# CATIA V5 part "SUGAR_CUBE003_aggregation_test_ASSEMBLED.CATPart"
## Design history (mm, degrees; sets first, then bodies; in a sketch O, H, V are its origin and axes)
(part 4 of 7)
Body30 "sugar_cube003_Bd002"
  Line194: type PtDir, RefPoint Point22, Direction edge [XY plane of AxisSystem1 | ZX plane of AxisSystem1], Start 0, End 5181.6 {= Body30.X1}
  Line195: type PtDir, RefPoint Point22, Direction edge [XY plane of AxisSystem1 | ZX plane of AxisSystem1], Start 0, End 5791.2 {= Body30.X2}
  Line196: type PtDir, RefPoint Point22, Direction edge [YZ plane of AxisSystem1 | XY plane of AxisSystem1], Start 0, End 5791.2 {= Body30.Y1}
  Line197: type PtDir, RefPoint Point22, Direction edge [YZ plane of AxisSystem1 | XY plane of AxisSystem1], Start 0, End 5486.4 {= Body30.Y2}
  Line198: type PtDir, RefPoint Point22, Direction edge [ZX plane of AxisSystem1 | YZ plane of AxisSystem1], Start 0, End 3962.4 {= Body30.Z1}
  Line199: type PtDir, RefPoint Point22, Direction edge [ZX plane of AxisSystem1 | YZ plane of AxisSystem1], Start 0, End 6096 {= Body30.Z2}
  Plane375: type Normal, Curve Line194, RefPoint vertex of Line194
  Plane376: type Normal, Curve Line195, RefPoint vertex of Line195
  Plane377: type Normal, Curve Line196, RefPoint vertex of Line196
  Plane378: type Normal, Curve Line197, RefPoint vertex of Line197
  Plane379: type Normal, Curve Line198, RefPoint vertex of Line198
  Plane380: type Normal, Curve Line199, RefPoint vertex of Line199
  Plane381: type 3Points, Element1 Point22, Element2 vertex of Line196, Element3 vertex of Line194
  Intersect561: ToIntersect1 Plane377, ToIntersect2 Plane376
  Intersect562: ToIntersect1 Plane375, ToIntersect2 Plane377
  Intersect563: ToIntersect1 Plane375, ToIntersect2 Plane378
  Intersect564: ToIntersect1 Plane378, ToIntersect2 Plane376
  MultiSel29
  LineCorner29: Elements ({intersect ToIntersect1 Plane381, ToIntersect2 Intersect563}; {intersect ToIntersect1 Plane381, ToIntersect2 Intersect564}; {intersect ToIntersect1 Plane381, ToIntersect2 Intersect561}; {intersect ToIntersect1 Plane381, ToIntersect2 Intersect562})
  Pad114: profile LineCorner29, up to Plane379, opposite side up to Plane380, deactivated
  Plane382: type Offset, RefPlane Plane378, Offset 609.6 {= thickness}
  Plane383: type Offset, RefPlane Plane377, Offset 609.6 {= thickness}, reversed
  Plane384: type Offset, RefPlane Plane375, Offset 609.6 {= thickness}, reversed
  Plane385: type Offset, RefPlane Plane376, Offset 609.6 {= thickness}
  Plane386: type Offset, RefPlane Plane380, Offset 609.6 {= thickness}
  Plane387: type Offset, RefPlane Plane379, Offset 609.6 {= thickness}, reversed
  Intersect565: ToIntersect1 Plane382, ToIntersect2 Plane375
  Intersect566: ToIntersect1 Plane383, ToIntersect2 Plane375
  Intersect567: ToIntersect1 Plane386, ToIntersect2 Plane375
  Intersect568: ToIntersect1 Plane387, ToIntersect2 Plane375
  Trim337: Trimmed (Intersect565; Intersect568)
  Trim338: Trimmed (Trim337; Intersect566)
  Trim339: Trimmed (Trim338; Intersect567)
  Pocket118: profile Trim339, up to Plane385, deactivated
  Pad115: profile LineCorner29, up to Plane379, opposite side up to Plane380, deactivated
  Intersect569: ToIntersect1 Plane383, ToIntersect2 Plane376
  Intersect570: ToIntersect1 Plane376, ToIntersect2 Plane382
  Intersect571: ToIntersect1 Plane386, ToIntersect2 Plane376
  Intersect572: ToIntersect1 Plane387, ToIntersect2 Plane376
  Trim340: Trimmed (Intersect572; Intersect569)
  Trim341: Trimmed (Trim340; Intersect571)
  Trim342: Trimmed (Trim341; Intersect570)
  Pocket119: profile Trim342, up to Plane384, deactivated
  Intersect573: ToIntersect1 Plane385, ToIntersect2 Plane378
  Intersect574: ToIntersect1 Plane386, ToIntersect2 Plane378
  Intersect575: ToIntersect1 Plane378, ToIntersect2 Plane384
  Intersect576: ToIntersect1 Plane387, ToIntersect2 Plane378
  Trim343: Trimmed (Intersect573; Intersect576)
  Trim344: Trimmed (Trim343; Intersect575)
  Trim345: Trimmed (Trim344; Intersect574)
  Pad116: profile LineCorner29, up to Plane379, opposite side up to Plane380, deactivated
  Pocket120: profile Trim345, up to Plane383, deactivated
  Intersect577: ToIntersect1 Plane384, ToIntersect2 Plane377
  Intersect578: ToIntersect1 Plane386, ToIntersect2 Plane377
  Intersect579: ToIntersect1 Plane385, ToIntersect2 Plane377
  Intersect580: ToIntersect1 Plane387, ToIntersect2 Plane377
  Trim346: Trimmed (Intersect577; Intersect580)
  Trim347: Trimmed (Trim346; Intersect579)
  Trim348: Trimmed (Trim347; Intersect578)
  Pad117: profile LineCorner29, up to Plane379, opposite side up to Plane380, deactivated
  Pocket121: profile Trim348, up to Plane382, deactivated
Body31 "sugar_cube003_Be002"
  Line200: type PtDir, RefPoint Point18, Direction edge [XY plane of AxisSystem1 | ZX plane of AxisSystem1], Start 0, End 4267.2 {= Body31.X1}
  Line201: type PtDir, RefPoint Point18, Direction edge [XY plane of AxisSystem1 | ZX plane of AxisSystem1], Start 0, End 3962.4 {= Body31.X2}
  Line202: type PtDir, RefPoint Point18, Direction edge [YZ plane of AxisSystem1 | XY plane of AxisSystem1], Start 0, End 5486.4 {= Body31.Y1}
  Line203: type PtDir, RefPoint Point18, Direction edge [YZ plane of AxisSystem1 | XY plane of AxisSystem1], Start 0, End 4876.8 {= Body31.Y2}
  Line204: type PtDir, RefPoint Point18, Direction edge [ZX plane of AxisSystem1 | YZ plane of AxisSystem1], Start 0, End 4876.8 {= Body31.Z1}
  Line205: type PtDir, RefPoint Point18, Direction edge [ZX plane of AxisSystem1 | YZ plane of AxisSystem1], Start 0, End 4572 {= Body31.Z2}
  Plane388: type Normal, Curve Line200, RefPoint vertex of Line200
  Plane389: type Normal, Curve Line201, RefPoint vertex of Line201
  Plane390: type Normal, Curve Line202, RefPoint vertex of Line202
  Plane391: type Normal, Curve Line203, RefPoint vertex of Line203
  Plane392: type Normal, Curve Line204, RefPoint vertex of Line204
  Plane393: type Normal, Curve Line205, RefPoint vertex of Line205
  Plane394: type 3Points, Element1 Point18, Element2 vertex of Line202, Element3 vertex of Line200
  Intersect581: ToIntersect1 Plane390, ToIntersect2 Plane389
  Intersect582: ToIntersect1 Plane388, ToIntersect2 Plane390
  Intersect583: ToIntersect1 Plane388, ToIntersect2 Plane391
  Intersect584: ToIntersect1 Plane391, ToIntersect2 Plane389
  MultiSel30
  LineCorner30: Elements ({intersect ToIntersect1 Plane394, ToIntersect2 Intersect583}; {intersect ToIntersect1 Plane394, ToIntersect2 Intersect584}; {intersect ToIntersect1 Plane394, ToIntersect2 Intersect581}; {intersect ToIntersect1 Plane394, ToIntersect2 Intersect582})
  Pad118: profile LineCorner30, up to Plane392, opposite side up to Plane393
  Plane395: type Offset, RefPlane Plane391, Offset 609.6 {= thickness}
  Plane396: type Offset, RefPlane Plane390, Offset 609.6 {= thickness}, reversed
  Plane397: type Offset, RefPlane Plane388, Offset 609.6 {= thickness}, reversed
  Plane398: type Offset, RefPlane Plane389, Offset 609.6 {= thickness}
  Plane399: type Offset, RefPlane Plane393, Offset 609.6 {= thickness}
  Plane400: type Offset, RefPlane Plane392, Offset 609.6 {= thickness}, reversed
  Intersect585: ToIntersect1 Plane395, ToIntersect2 Plane388
  Intersect586: ToIntersect1 Plane396, ToIntersect2 Plane388
  Intersect587: ToIntersect1 Plane399, ToIntersect2 Plane388
  Intersect588: ToIntersect1 Plane400, ToIntersect2 Plane388
  Trim349: Trimmed (Intersect585; Intersect588)
  Trim350: Trimmed (Trim349; Intersect586)
  Trim351: Trimmed (Trim350; Intersect587)
  Pocket122: profile Trim351, up to Plane398, deactivated
  Pad119: profile LineCorner30, up to Plane392, opposite side up to Plane393, deactivated
  Intersect589: ToIntersect1 Plane396, ToIntersect2 Plane389
  Intersect590: ToIntersect1 Plane389, ToIntersect2 Plane395
  Intersect591: ToIntersect1 Plane399, ToIntersect2 Plane389
  Intersect592: ToIntersect1 Plane400, ToIntersect2 Plane389
  Trim352: Trimmed (Intersect592; Intersect589)
  Trim353: Trimmed (Trim352; Intersect591)
  Trim354: Trimmed (Trim353; Intersect590)
  Pocket123: profile Trim354, up to Plane397, deactivated
  Intersect593: ToIntersect1 Plane398, ToIntersect2 Plane391
  Intersect594: ToIntersect1 Plane399, ToIntersect2 Plane391
  Intersect595: ToIntersect1 Plane391, ToIntersect2 Plane397
  Intersect596: ToIntersect1 Plane400, ToIntersect2 Plane391
  Trim355: Trimmed (Intersect593; Intersect596)
  Trim356: Trimmed (Trim355; Intersect595)
  Trim357: Trimmed (Trim356; Intersect594)
  Pad120: profile LineCorner30, up to Plane392, opposite side up to Plane393, deactivated
  Pocket124: profile Trim357, up to Plane396, deactivated
  Intersect597: ToIntersect1 Plane397, ToIntersect2 Plane390
  Intersect598: ToIntersect1 Plane399, ToIntersect2 Plane390
  Intersect599: ToIntersect1 Plane398, ToIntersect2 Plane390
  Intersect600: ToIntersect1 Plane400, ToIntersect2 Plane390
  Trim358: Trimmed (Intersect597; Intersect600)
  Trim359: Trimmed (Trim358; Intersect599)
  Trim360: Trimmed (Trim359; Intersect598)
  Pad121: profile LineCorner30, up to Plane392, opposite side up to Plane393, deactivated
  Pocket125: profile Trim360, up to Plane395, deactivated
Body32 "sugar_cube003_Ba003"
  Line206: type PtDir, RefPoint Point35, Direction edge [XY plane of AxisSystem1 | ZX plane of AxisSystem1], Start 0, End 3048 {= Body32.X1}
  Line207: type PtDir, RefPoint Point35, Direction edge [XY plane of AxisSystem1 | ZX plane of AxisSystem1], Start 0, End 3962.4 {= Body32.X2}
  Line208: type PtDir, RefPoint Point35, Direction edge [YZ plane of AxisSystem1 | XY plane of AxisSystem1], Start 0, End 5791.2 {= Body32.Y1}
  Line209: type PtDir, RefPoint Point35, Direction edge [YZ plane of AxisSystem1 | XY plane of AxisSystem1], Start 0, End 3048 {= Body32.Y2}
  Line210: type PtDir, RefPoint Point35, Direction edge [ZX plane of AxisSystem1 | YZ plane of AxisSystem1], Start 0, End 5181.6 {= Body32.Z1}
  Line211: type PtDir, RefPoint Point35, Direction edge [ZX plane of AxisSystem1 | YZ plane of AxisSystem1], Start 0, End 4572 {= Body32.Z2}
  Plane401: type Normal, Curve Line206, RefPoint vertex of Line206
  Plane402: type Normal, Curve Line207, RefPoint vertex of Line207
  Plane403: type Normal, Curve Line208, RefPoint vertex of Line208
  Plane404: type Normal, Curve Line209, RefPoint vertex of Line209
  Plane405: type Normal, Curve Line210, RefPoint vertex of Line210
  Plane406: type Normal, Curve Line211, RefPoint vertex of Line211
  Plane407: type 3Points, Element1 Point35, Element2 vertex of Line208, Element3 vertex of Line206
  Intersect601: ToIntersect1 Plane403, ToIntersect2 Plane402
  Intersect602: ToIntersect1 Plane401, ToIntersect2 Plane403
  Intersect603: ToIntersect1 Plane401, ToIntersect2 Plane404
  Intersect604: ToIntersect1 Plane404, ToIntersect2 Plane402
  MultiSel31
  LineCorner31: Elements ({intersect ToIntersect1 Plane407, ToIntersect2 Intersect603}; {intersect ToIntersect1 Plane407, ToIntersect2 Intersect604}; {intersect ToIntersect1 Plane407, ToIntersect2 Intersect601}; {intersect ToIntersect1 Plane407, ToIntersect2 Intersect602})
  Pad122: profile LineCorner31, up to Plane405, opposite side up to Plane406, deactivated
  Plane408: type Offset, RefPlane Plane404, Offset 609.6 {= thickness}
  Plane409: type Offset, RefPlane Plane403, Offset 609.6 {= thickness}, reversed
  Plane410: type Offset, RefPlane Plane401, Offset 609.6 {= thickness}, reversed
  Plane411: type Offset, RefPlane Plane402, Offset 609.6 {= thickness}
  Plane412: type Offset, RefPlane Plane406, Offset 609.6 {= thickness}
  Plane413: type Offset, RefPlane Plane405, Offset 609.6 {= thickness}, reversed
  Intersect605: ToIntersect1 Plane408, ToIntersect2 Plane401
  Intersect606: ToIntersect1 Plane409, ToIntersect2 Plane401
  Intersect607: ToIntersect1 Plane412, ToIntersect2 Plane401
  Intersect608: ToIntersect1 Plane413, ToIntersect2 Plane401
  Trim361: Trimmed (Intersect605; Intersect608)
  Trim362: Trimmed (Trim361; Intersect606)
  Trim363: Trimmed (Trim362; Intersect607)
  Pocket126: profile Trim363, up to Plane411, deactivated
  Pad123: profile LineCorner31, up to Plane405, opposite side up to Plane406, deactivated
  Intersect609: ToIntersect1 Plane409, ToIntersect2 Plane402
  Intersect610: ToIntersect1 Plane402, ToIntersect2 Plane408
  Intersect611: ToIntersect1 Plane412, ToIntersect2 Plane402
  Intersect612: ToIntersect1 Plane413, ToIntersect2 Plane402
  Trim364: Trimmed (Intersect612; Intersect609)
  Trim365: Trimmed (Trim364; Intersect611)
  Trim366: Trimmed (Trim365; Intersect610)
  Pocket127: profile Trim366, up to Plane410, deactivated
  Intersect613: ToIntersect1 Plane411, ToIntersect2 Plane404
  Intersect614: ToIntersect1 Plane412, ToIntersect2 Plane404
  Intersect615: ToIntersect1 Plane404, ToIntersect2 Plane410
  Intersect616: ToIntersect1 Plane413, ToIntersect2 Plane404
  Trim367: Trimmed (Intersect613; Intersect616)
  Trim368: Trimmed (Trim367; Intersect615)
  Trim369: Trimmed (Trim368; Intersect614)
  Pad124: profile LineCorner31, up to Plane405, opposite side up to Plane406, deactivated
  Pocket128: profile Trim369, up to Plane409, deactivated
  Intersect617: ToIntersect1 Plane410, ToIntersect2 Plane403
  Intersect618: ToIntersect1 Plane412, ToIntersect2 Plane403
  Intersect619: ToIntersect1 Plane411, ToIntersect2 Plane403
  Intersect620: ToIntersect1 Plane413, ToIntersect2 Plane403
  Trim370: Trimmed (Intersect617; Intersect620)
  Trim371: Trimmed (Trim370; Intersect619)
  Trim372: Trimmed (Trim371; Intersect618)
  Pad125: profile LineCorner31, up to Plane405, opposite side up to Plane406, deactivated
  Pocket129: profile Trim372, up to Plane408, deactivated
Body33 "sugar_cube003Bb003"
  Line212: type PtDir, RefPoint Point31, Direction edge [XY plane of AxisSystem1 | ZX plane of AxisSystem1], Start 0, End 5791.2 {= Body33.X1}
  Line213: type PtDir, RefPoint Point31, Direction edge [XY plane of AxisSystem1 | ZX plane of AxisSystem1], Start 0, End 4267.2 {= Body33.X2}
  Line214: type PtDir, RefPoint Point31, Direction edge [YZ plane of AxisSystem1 | XY plane of AxisSystem1], Start 0, End 5486.4 {= Body33.Y1}
  Line215: type PtDir, RefPoint Point31, Direction edge [YZ plane of AxisSystem1 | XY plane of AxisSystem1], Start 0, End 6096 {= Body33.Y2}
  Line216: type PtDir, RefPoint Point31, Direction edge [ZX plane of AxisSystem1 | YZ plane of AxisSystem1], Start 0, End 4267.2 {= Body33.Z1}
  Line217: type PtDir, RefPoint Point31, Direction edge [ZX plane of AxisSystem1 | YZ plane of AxisSystem1], Start 0, End 5486.4 {= Body33.Z2}
  Plane414: type Normal, Curve Line212, RefPoint vertex of Line212
  Plane415: type Normal, Curve Line213, RefPoint vertex of Line213
  Plane416: type Normal, Curve Line214, RefPoint vertex of Line214
  Plane417: type Normal, Curve Line215, RefPoint vertex of Line215
  Plane418: type Normal, Curve Line216, RefPoint vertex of Line216
  Plane419: type Normal, Curve Line217, RefPoint vertex of Line217
  Plane420: type 3Points, Element1 Point31, Element2 vertex of Line214, Element3 vertex of Line212
  Intersect621: ToIntersect1 Plane416, ToIntersect2 Plane415
  Intersect622: ToIntersect1 Plane414, ToIntersect2 Plane416
  Intersect623: ToIntersect1 Plane414, ToIntersect2 Plane417
  Intersect624: ToIntersect1 Plane417, ToIntersect2 Plane415
  MultiSel32
  LineCorner32: Elements ({intersect ToIntersect1 Plane420, ToIntersect2 Intersect623}; {intersect ToIntersect1 Plane420, ToIntersect2 Intersect624}; {intersect ToIntersect1 Plane420, ToIntersect2 Intersect621}; {intersect ToIntersect1 Plane420, ToIntersect2 Intersect622})
  Pad126: profile LineCorner32, up to Plane418, opposite side up to Plane419
  Plane421: type Offset, RefPlane Plane417, Offset 609.6 {= thickness}
  Plane422: type Offset, RefPlane Plane416, Offset 609.6 {= thickness}, reversed
  Plane423: type Offset, RefPlane Plane414, Offset 609.6 {= thickness}, reversed
  Plane424: type Offset, RefPlane Plane415, Offset 609.6 {= thickness}
  Plane425: type Offset, RefPlane Plane419, Offset 609.6 {= thickness}
  Plane426: type Offset, RefPlane Plane418, Offset 609.6 {= thickness}, reversed
  Intersect625: ToIntersect1 Plane421, ToIntersect2 Plane414
  Intersect626: ToIntersect1 Plane422, ToIntersect2 Plane414
  Intersect627: ToIntersect1 Plane425, ToIntersect2 Plane414
  Intersect628: ToIntersect1 Plane426, ToIntersect2 Plane414
  Trim373: Trimmed (Intersect625; Intersect628)
  Trim374: Trimmed (Trim373; Intersect626)
  Trim375: Trimmed (Trim374; Intersect627)
  Pocket130: profile Trim375, up to Plane424, deactivated
  Pad127: profile LineCorner32, up to Plane418, opposite side up to Plane419, deactivated
  Intersect629: ToIntersect1 Plane422, ToIntersect2 Plane415
  Intersect630: ToIntersect1 Plane415, ToIntersect2 Plane421
  Intersect631: ToIntersect1 Plane425, ToIntersect2 Plane415
  Intersect632: ToIntersect1 Plane426, ToIntersect2 Plane415
  Trim376: Trimmed (Intersect632; Intersect629)
  Trim377: Trimmed (Trim376; Intersect631)
  Trim378: Trimmed (Trim377; Intersect630)
  Pocket131: profile Trim378, up to Plane423, deactivated
  Intersect633: ToIntersect1 Plane424, ToIntersect2 Plane417
  Intersect634: ToIntersect1 Plane425, ToIntersect2 Plane417
  Intersect635: ToIntersect1 Plane417, ToIntersect2 Plane423
  Intersect636: ToIntersect1 Plane426, ToIntersect2 Plane417
  Trim379: Trimmed (Intersect633; Intersect636)
  Trim380: Trimmed (Trim379; Intersect635)
  Trim381: Trimmed (Trim380; Intersect634)
  Pad128: profile LineCorner32, up to Plane418, opposite side up to Plane419, deactivated
  Pocket132: profile Trim381, up to Plane422, deactivated
  Intersect637: ToIntersect1 Plane423, ToIntersect2 Plane416
  Intersect638: ToIntersect1 Plane425, ToIntersect2 Plane416
  Intersect639: ToIntersect1 Plane424, ToIntersect2 Plane416
  Intersect640: ToIntersect1 Plane426, ToIntersect2 Plane416
  Trim382: Trimmed (Intersect637; Intersect640)
  Trim383: Trimmed (Trim382; Intersect639)
  Trim384: Trimmed (Trim383; Intersect638)
  Pad129: profile LineCorner32, up to Plane418, opposite side up to Plane419, deactivated
  Pocket133: profile Trim384, up to Plane421, deactivated
Body34 "Bc003"
  Line218: type PtDir, RefPoint Point27, Direction edge [XY plane of AxisSystem1 | ZX plane of AxisSystem1], Start 0, End 5791.2 {= Body34.X1}
  Line219: type PtDir, RefPoint Point27, Direction edge [XY plane of AxisSystem1 | ZX plane of AxisSystem1], Start 0, End 5486.4 {= Body34.X2}
  Line220: type PtDir, RefPoint Point27, Direction edge [YZ plane of AxisSystem1 | XY plane of AxisSystem1], Start 0, End 3352.8 {= Body34.Y1}
  Line221: type PtDir, RefPoint Point27, Direction edge [YZ plane of AxisSystem1 | XY plane of AxisSystem1], Start 0, End 6096 {= Body34.Y2}
  Line222: type PtDir, RefPoint Point27, Direction edge [ZX plane of AxisSystem1 | YZ plane of AxisSystem1], Start 0, End 4267.2 {= Body34.Z1}
  Line223: type PtDir, RefPoint Point27, Direction edge [ZX plane of AxisSystem1 | YZ plane of AxisSystem1], Start 0, End 5181.6 {= Body34.Z2}
  Plane427: type Normal, Curve Line218, RefPoint vertex of Line218
  Plane428: type Normal, Curve Line219, RefPoint vertex of Line219
  Plane429: type Normal, Curve Line220, RefPoint vertex of Line220
  Plane430: type Normal, Curve Line221, RefPoint vertex of Line221
  Plane431: type Normal, Curve Line222, RefPoint vertex of Line222
  Plane432: type Normal, Curve Line223, RefPoint vertex of Line223
  Plane433: type 3Points, Element1 Point27, Element2 vertex of Line220, Element3 vertex of Line218
  Intersect641: ToIntersect1 Plane429, ToIntersect2 Plane428
  Intersect642: ToIntersect1 Plane427, ToIntersect2 Plane429
  Intersect643: ToIntersect1 Plane427, ToIntersect2 Plane430
  Intersect644: ToIntersect1 Plane430, ToIntersect2 Plane428
  MultiSel33
  LineCorner33: Elements ({intersect ToIntersect1 Plane433, ToIntersect2 Intersect643}; {intersect ToIntersect1 Plane433, ToIntersect2 Intersect644}; {intersect ToIntersect1 Plane433, ToIntersect2 Intersect641}; {intersect ToIntersect1 Plane433, ToIntersect2 Intersect642})
  Pad130: profile LineCorner33, up to Plane431, opposite side up to Plane432
  Plane434: type Offset, RefPlane Plane430, Offset 609.6 {= thickness}
  Plane435: type Offset, RefPlane Plane429, Offset 609.6 {= thickness}, reversed
  Plane436: type Offset, RefPlane Plane427, Offset 609.6 {= thickness}, reversed
  Plane437: type Offset, RefPlane Plane428, Offset 609.6 {= thickness}
  Plane438: type Offset, RefPlane Plane432, Offset 609.6 {= thickness}
  Plane439: type Offset, RefPlane Plane431, Offset 609.6 {= thickness}, reversed
  Intersect645: ToIntersect1 Plane434, ToIntersect2 Plane427
  Intersect646: ToIntersect1 Plane435, ToIntersect2 Plane427
  Intersect647: ToIntersect1 Plane438, ToIntersect2 Plane427
  Intersect648: ToIntersect1 Plane439, ToIntersect2 Plane427
  Trim385: Trimmed (Intersect645; Intersect648)
  Trim386: Trimmed (Trim385; Intersect646)
  Trim387: Trimmed (Trim386; Intersect647)
  Pocket134: profile Trim387, up to Plane437, deactivated
  Pad131: profile LineCorner33, up to Plane431, opposite side up to Plane432, deactivated
  Intersect649: ToIntersect1 Plane435, ToIntersect2 Plane428
  Intersect650: ToIntersect1 Plane428, ToIntersect2 Plane434
  Intersect651: ToIntersect1 Plane438, ToIntersect2 Plane428
  Intersect652: ToIntersect1 Plane439, ToIntersect2 Plane428
  Trim388: Trimmed (Intersect652; Intersect649)
  Trim389: Trimmed (Trim388; Intersect651)
  Trim390: Trimmed (Trim389; Intersect650)
  Pocket135: profile Trim390, up to Plane436, deactivated
  Intersect653: ToIntersect1 Plane437, ToIntersect2 Plane430
  Intersect654: ToIntersect1 Plane438, ToIntersect2 Plane430
  Intersect655: ToIntersect1 Plane430, ToIntersect2 Plane436
  Intersect656: ToIntersect1 Plane439, ToIntersect2 Plane430
  Trim391: Trimmed (Intersect653; Intersect656)
  Trim392: Trimmed (Trim391; Intersect655)
  Trim393: Trimmed (Trim392; Intersect654)
  Pad132: profile LineCorner33, up to Plane431, opposite side up to Plane432, deactivated
  Pocket136: profile Trim393, up to Plane435, deactivated
  Intersect657: ToIntersect1 Plane436, ToIntersect2 Plane429
  Intersect658: ToIntersect1 Plane438, ToIntersect2 Plane429
  Intersect659: ToIntersect1 Plane437, ToIntersect2 Plane429
  Intersect660: ToIntersect1 Plane439, ToIntersect2 Plane429
  Trim394: Trimmed (Intersect657; Intersect660)
  Trim395: Trimmed (Trim394; Intersect659)
  Trim396: Trimmed (Trim395; Intersect658)
  Pad133: profile LineCorner33, up to Plane431, opposite side up to Plane432, deactivated
  Pocket137: profile Trim396, up to Plane434, deactivated
Body35 "sugar_cube003Bd003"
  Line224: type PtDir, RefPoint Point23, Direction edge [XY plane of AxisSystem1 | ZX plane of AxisSystem1], Start 0, End 3962.4 {= Body35.X1}
  Line225: type PtDir, RefPoint Point23, Direction edge [XY plane of AxisSystem1 | ZX plane of AxisSystem1], Start 0, End 4572 {= Body35.X2}
  Line226: type PtDir, RefPoint Point23, Direction edge [YZ plane of AxisSystem1 | XY plane of AxisSystem1], Start 0, End 5181.6 {= Body35.Y1}
  Line227: type PtDir, RefPoint Point23, Direction edge [YZ plane of AxisSystem1 | XY plane of AxisSystem1], Start 0, End 4572 {= Body35.Y2}
  Line228: type PtDir, RefPoint Point23, Direction edge [ZX plane of AxisSystem1 | YZ plane of AxisSystem1], Start 0, End 5181.6 {= Body35.Z1}
  Line229: type PtDir, RefPoint Point23, Direction edge [ZX plane of AxisSystem1 | YZ plane of AxisSystem1], Start 0, End 5486.4 {= Body35.Z2}
  Plane440: type Normal, Curve Line224, RefPoint vertex of Line224
  Plane441: type Normal, Curve Line225, RefPoint vertex of Line225
  Plane442: type Normal, Curve Line226, RefPoint vertex of Line226
  Plane443: type Normal, Curve Line227, RefPoint vertex of Line227
  Plane444: type Normal, Curve Line228, RefPoint vertex of Line228
  Plane445: type Normal, Curve Line229, RefPoint vertex of Line229
  Plane446: type 3Points, Element1 Point23, Element2 vertex of Line226, Element3 vertex of Line224
  Intersect661: ToIntersect1 Plane442, ToIntersect2 Plane441
  Intersect662: ToIntersect1 Plane440, ToIntersect2 Plane442
  Intersect663: ToIntersect1 Plane440, ToIntersect2 Plane443
  Intersect664: ToIntersect1 Plane443, ToIntersect2 Plane441
  MultiSel34
  LineCorner34: Elements ({intersect ToIntersect1 Plane446, ToIntersect2 Intersect663}; {intersect ToIntersect1 Plane446, ToIntersect2 Intersect664}; {intersect ToIntersect1 Plane446, ToIntersect2 Intersect661}; {intersect ToIntersect1 Plane446, ToIntersect2 Intersect662})
  Pad134: profile LineCorner34, up to Plane444, opposite side up to Plane445
  Plane447: type Offset, RefPlane Plane443, Offset 609.6 {= thickness}
  Plane448: type Offset, RefPlane Plane442, Offset 609.6 {= thickness}, reversed
  Plane449: type Offset, RefPlane Plane440, Offset 609.6 {= thickness}, reversed
  Plane450: type Offset, RefPlane Plane441, Offset 609.6 {= thickness}
  Plane451: type Offset, RefPlane Plane445, Offset 609.6 {= thickness}
  Plane452: type Offset, RefPlane Plane444, Offset 609.6 {= thickness}, reversed
  Intersect665: ToIntersect1 Plane447, ToIntersect2 Plane440
  Intersect666: ToIntersect1 Plane448, ToIntersect2 Plane440
  Intersect667: ToIntersect1 Plane451, ToIntersect2 Plane440
  Intersect668: ToIntersect1 Plane452, ToIntersect2 Plane440
  Trim397: Trimmed (Intersect665; Intersect668)
  Trim398: Trimmed (Trim397; Intersect666)
  Trim399: Trimmed (Trim398; Intersect667)
  Pocket138: profile Trim399, up to Plane450
  Pad135: profile LineCorner34, up to Plane444, opposite side up to Plane445, deactivated
  Intersect669: ToIntersect1 Plane448, ToIntersect2 Plane441
  Intersect670: ToIntersect1 Plane441, ToIntersect2 Plane447
  Intersect671: ToIntersect1 Plane451, ToIntersect2 Plane441
  Intersect672: ToIntersect1 Plane452, ToIntersect2 Plane441
  Trim400: Trimmed (Intersect672; Intersect669)
  Trim401: Trimmed (Trim400; Intersect671)
  Trim402: Trimmed (Trim401; Intersect670)
  Pocket139: profile Trim402, up to Plane449, deactivated
  Intersect673: ToIntersect1 Plane450, ToIntersect2 Plane443
  Intersect674: ToIntersect1 Plane451, ToIntersect2 Plane443
  Intersect675: ToIntersect1 Plane443, ToIntersect2 Plane449
  Intersect676: ToIntersect1 Plane452, ToIntersect2 Plane443
  Trim403: Trimmed (Intersect673; Intersect676)
  Trim404: Trimmed (Trim403; Intersect675)
  Trim405: Trimmed (Trim404; Intersect674)
  Pad136: profile LineCorner34, up to Plane444, opposite side up to Plane445, deactivated
  Pocket140: profile Trim405, up to Plane448, deactivated
  Intersect677: ToIntersect1 Plane449, ToIntersect2 Plane442
  Intersect678: ToIntersect1 Plane451, ToIntersect2 Plane442
  Intersect679: ToIntersect1 Plane450, ToIntersect2 Plane442
  Intersect680: ToIntersect1 Plane452, ToIntersect2 Plane442
  Trim406: Trimmed (Intersect677; Intersect680)
  Trim407: Trimmed (Trim406; Intersect679)
  Trim408: Trimmed (Trim407; Intersect678)
  Pad137: profile LineCorner34, up to Plane444, opposite side up to Plane445, deactivated
  Pocket141: profile Trim408, up to Plane447, deactivated
Body36 "sugar_cube003Be003"
  Line230: type PtDir, RefPoint Point19, Direction edge [XY plane of AxisSystem1 | ZX plane of AxisSystem1], Start 0, End 4572 {= Body36.X1}
  Line231: type PtDir, RefPoint Point19, Direction edge [XY plane of AxisSystem1 | ZX plane of AxisSystem1], Start 0, End 6096 {= Body36.X2}
  Line232: type PtDir, RefPoint Point19, Direction edge [YZ plane of AxisSystem1 | XY plane of AxisSystem1], Start 0, End 3657.6 {= Body36.Y1}
  Line233: type PtDir, RefPoint Point19, Direction edge [YZ plane of AxisSystem1 | XY plane of AxisSystem1], Start 0, End 4572 {= Body36.Y2}
  Line234: type PtDir, RefPoint Point19, Direction edge [ZX plane of AxisSystem1 | YZ plane of AxisSystem1], Start 0, End 3352.8 {= Body36.Z1}
  Line235: type PtDir, RefPoint Point19, Direction edge [ZX plane of AxisSystem1 | YZ plane of AxisSystem1], Start 0, End 4267.2 {= Body36.Z2}
  Plane453: type Normal, Curve Line230, RefPoint vertex of Line230
  Plane454: type Normal, Curve Line231, RefPoint vertex of Line231
  Plane455: type Normal, Curve Line232, RefPoint vertex of Line232
  Plane456: type Normal, Curve Line233, RefPoint vertex of Line233
  Plane457: type Normal, Curve Line234, RefPoint vertex of Line234
  Plane458: type Normal, Curve Line235, RefPoint vertex of Line235
  Plane459: type 3Points, Element1 Point19, Element2 vertex of Line232, Element3 vertex of Line230
  Intersect681: ToIntersect1 Plane455, ToIntersect2 Plane454
  Intersect682: ToIntersect1 Plane453, ToIntersect2 Plane455
  Intersect683: ToIntersect1 Plane453, ToIntersect2 Plane456
  Intersect684: ToIntersect1 Plane456, ToIntersect2 Plane454
  MultiSel35
  LineCorner35: Elements ({intersect ToIntersect1 Plane459, ToIntersect2 Intersect683}; {intersect ToIntersect1 Plane459, ToIntersect2 Intersect684}; {intersect ToIntersect1 Plane459, ToIntersect2 Intersect681}; {intersect ToIntersect1 Plane459, ToIntersect2 Intersect682})
  Pad138: profile LineCorner35, up to Plane457, opposite side up to Plane458
  Plane460: type Offset, RefPlane Plane456, Offset 609.6 {= thickness}
  Plane461: type Offset, RefPlane Plane455, Offset 609.6 {= thickness}, reversed
  Plane462: type Offset, RefPlane Plane453, Offset 609.6 {= thickness}, reversed
  Plane463: type Offset, RefPlane Plane454, Offset 609.6 {= thickness}
  Plane464: type Offset, RefPlane Plane458, Offset 609.6 {= thickness}
  Plane465: type Offset, RefPlane Plane457, Offset 609.6 {= thickness}, reversed
  Intersect685: ToIntersect1 Plane460, ToIntersect2 Plane453
  Intersect686: ToIntersect1 Plane461, ToIntersect2 Plane453
  Intersect687: ToIntersect1 Plane464, ToIntersect2 Plane453
  Intersect688: ToIntersect1 Plane465, ToIntersect2 Plane453
  Trim409: Trimmed (Intersect685; Intersect688)
  Trim410: Trimmed (Trim409; Intersect686)
  Trim411: Trimmed (Trim410; Intersect687)
  Pocket142: profile Trim411, up to Plane463, deactivated
  Pad139: profile LineCorner35, up to Plane457, opposite side up to Plane458, deactivated
  Intersect689: ToIntersect1 Plane461, ToIntersect2 Plane454
  Intersect690: ToIntersect1 Plane454, ToIntersect2 Plane460
  Intersect691: ToIntersect1 Plane464, ToIntersect2 Plane454
  Intersect692: ToIntersect1 Plane465, ToIntersect2 Plane454
  Trim412: Trimmed (Intersect692; Intersect689)
  Trim413: Trimmed (Trim412; Intersect691)
  Trim414: Trimmed (Trim413; Intersect690)
  Pocket143: profile Trim414, up to Plane462, deactivated
  Intersect693: ToIntersect1 Plane463, ToIntersect2 Plane456
  Intersect694: ToIntersect1 Plane464, ToIntersect2 Plane456
  Intersect695: ToIntersect1 Plane456, ToIntersect2 Plane462
  Intersect696: ToIntersect1 Plane465, ToIntersect2 Plane456
  Trim415: Trimmed (Intersect693; Intersect696)
  Trim416: Trimmed (Trim415; Intersect695)
  Trim417: Trimmed (Trim416; Intersect694)
  Pad140: profile LineCorner35, up to Plane457, opposite side up to Plane458, deactivated
  Pocket144: profile Trim417, up to Plane461, deactivated
  Intersect697: ToIntersect1 Plane462, ToIntersect2 Plane455
  Intersect698: ToIntersect1 Plane464, ToIntersect2 Plane455
  Intersect699: ToIntersect1 Plane463, ToIntersect2 Plane455
  Intersect700: ToIntersect1 Plane465, ToIntersect2 Plane455
  Trim418: Trimmed (Intersect697; Intersect700)
  Trim419: Trimmed (Trim418; Intersect699)
  Trim420: Trimmed (Trim419; Intersect698)
  Pad141: profile LineCorner35, up to Plane457, opposite side up to Plane458, deactivated
  Pocket145: profile Trim420, up to Plane460, deactivated
Body37 "sugar_cube003_Ba004"
  Line236: type PtDir, RefPoint Point36, Direction edge [XY plane of AxisSystem1 | ZX plane of AxisSystem1], Start 0, End 3352.8 {= Body37.X1}
  Line237: type PtDir, RefPoint Point36, Direction edge [XY plane of AxisSystem1 | ZX plane of AxisSystem1], Start 0, End 3352.8 {= Body37.X2}
  Line238: type PtDir, RefPoint Point36, Direction edge [YZ plane of AxisSystem1 | XY plane of AxisSystem1], Start 0, End 4572 {= Body37.Y1}
  Line239: type PtDir, RefPoint Point36, Direction edge [YZ plane of AxisSystem1 | XY plane of AxisSystem1], Start 0, End 4267.2 {= Body37.Y2}
  Line240: type PtDir, RefPoint Point36, Direction edge [ZX plane of AxisSystem1 | YZ plane of AxisSystem1], Start 0, End 3352.8 {= Body37.Z1}
  Line241: type PtDir, RefPoint Point36, Direction edge [ZX plane of AxisSystem1 | YZ plane of AxisSystem1], Start 0, End 5181.6 {= Body37.Z2}
  Plane466: type Normal, Curve Line236, RefPoint vertex of Line236
  Plane467: type Normal, Curve Line237, RefPoint vertex of Line237
  Plane468: type Normal, Curve Line238, RefPoint vertex of Line238
  Plane469: type Normal, Curve Line239, RefPoint vertex of Line239
  Plane470: type Normal, Curve Line240, RefPoint vertex of Line240
  Plane471: type Normal, Curve Line241, RefPoint vertex of Line241
  Plane472: type 3Points, Element1 Point36, Element2 vertex of Line238, Element3 vertex of Line236
  Intersect701: ToIntersect1 Plane468, ToIntersect2 Plane467
  Intersect702: ToIntersect1 Plane466, ToIntersect2 Plane468
  Intersect703: ToIntersect1 Plane466, ToIntersect2 Plane469
  Intersect704: ToIntersect1 Plane469, ToIntersect2 Plane467
  MultiSel36
  LineCorner36: Elements ({intersect ToIntersect1 Plane472, ToIntersect2 Intersect703}; {intersect ToIntersect1 Plane472, ToIntersect2 Intersect704}; {intersect ToIntersect1 Plane472, ToIntersect2 Intersect701}; {intersect ToIntersect1 Plane472, ToIntersect2 Intersect702})
  Pad142: profile LineCorner36, up to Plane470, opposite side up to Plane471
  Plane473: type Offset, RefPlane Plane469, Offset 609.6 {= thickness}
  Plane474: type Offset, RefPlane Plane468, Offset 609.6 {= thickness}, reversed
  Plane475: type Offset, RefPlane Plane466, Offset 609.6 {= thickness}, reversed
  Plane476: type Offset, RefPlane Plane467, Offset 609.6 {= thickness}
  Plane477: type Offset, RefPlane Plane471, Offset 609.6 {= thickness}
  Plane478: type Offset, RefPlane Plane470, Offset 609.6 {= thickness}, reversed
  Intersect705: ToIntersect1 Plane473, ToIntersect2 Plane466
  Intersect706: ToIntersect1 Plane474, ToIntersect2 Plane466
  Intersect707: ToIntersect1 Plane477, ToIntersect2 Plane466
  Intersect708: ToIntersect1 Plane478, ToIntersect2 Plane466
  Trim421: Trimmed (Intersect705; Intersect708)
  Trim422: Trimmed (Trim421; Intersect706)
  Trim423: Trimmed (Trim422; Intersect707)
  Pocket146: profile Trim423, up to Plane476, deactivated
  Pad143: profile LineCorner36, up to Plane470, opposite side up to Plane471, deactivated
  Intersect709: ToIntersect1 Plane474, ToIntersect2 Plane467
  Intersect710: ToIntersect1 Plane467, ToIntersect2 Plane473
  Intersect711: ToIntersect1 Plane477, ToIntersect2 Plane467
  Intersect712: ToIntersect1 Plane478, ToIntersect2 Plane467
  Trim424: Trimmed (Intersect712; Intersect709)
  Trim425: Trimmed (Trim424; Intersect711)
  Trim426: Trimmed (Trim425; Intersect710)
  Pocket147: profile Trim426, up to Plane475, deactivated
  Intersect713: ToIntersect1 Plane476, ToIntersect2 Plane469
  Intersect714: ToIntersect1 Plane477, ToIntersect2 Plane469
  Intersect715: ToIntersect1 Plane469, ToIntersect2 Plane475
  Intersect716: ToIntersect1 Plane478, ToIntersect2 Plane469
  Trim427: Trimmed (Intersect713; Intersect716)
  Trim428: Trimmed (Trim427; Intersect715)
  Trim429: Trimmed (Trim428; Intersect714)
  Pad144: profile LineCorner36, up to Plane470, opposite side up to Plane471, deactivated
  Pocket148: profile Trim429, up to Plane474, deactivated
  Intersect717: ToIntersect1 Plane475, ToIntersect2 Plane468
  Intersect718: ToIntersect1 Plane477, ToIntersect2 Plane468
  Intersect719: ToIntersect1 Plane476, ToIntersect2 Plane468
  Intersect720: ToIntersect1 Plane478, ToIntersect2 Plane468
  Trim430: Trimmed (Intersect717; Intersect720)
  Trim431: Trimmed (Trim430; Intersect719)
  Trim432: Trimmed (Trim431; Intersect718)
  Pad145: profile LineCorner36, up to Plane470, opposite side up to Plane471, deactivated
  Pocket149: profile Trim432, up to Plane473, deactivated
Body38 "sugar_cube003Bb004"
  Line242: type PtDir, RefPoint Point32, Direction edge [XY plane of AxisSystem1 | ZX plane of AxisSystem1], Start 0, End 4267.2 {= Body38.X1}
  Line243: type PtDir, RefPoint Point32, Direction edge [XY plane of AxisSystem1 | ZX plane of AxisSystem1], Start 0, End 4267.2 {= Body38.X2}
  Line244: type PtDir, RefPoint Point32, Direction edge [YZ plane of AxisSystem1 | XY plane of AxisSystem1], Start 0, End 4876.8 {= Body38.Y1}
  Line245: type PtDir, RefPoint Point32, Direction edge [YZ plane of AxisSystem1 | XY plane of AxisSystem1], Start 0, End 4876.8 {= Body38.Y2}
  Line246: type PtDir, RefPoint Point32, Direction edge [ZX plane of AxisSystem1 | YZ plane of AxisSystem1], Start 0, End 4267.2 {= Body38.Z1}
  Line247: type PtDir, RefPoint Point32, Direction edge [ZX plane of AxisSystem1 | YZ plane of AxisSystem1], Start 0, End 6096 {= Body38.Z2}
  Plane479: type Normal, Curve Line242, RefPoint vertex of Line242
  Plane480: type Normal, Curve Line243, RefPoint vertex of Line243
  Plane481: type Normal, Curve Line244, RefPoint vertex of Line244
  Plane482: type Normal, Curve Line245, RefPoint vertex of Line245
  Plane483: type Normal, Curve Line246, RefPoint vertex of Line246
  Plane484: type Normal, Curve Line247, RefPoint vertex of Line247
  Plane485: type 3Points, Element1 Point32, Element2 vertex of Line244, Element3 vertex of Line242
  Intersect721: ToIntersect1 Plane481, ToIntersect2 Plane480
  Intersect722: ToIntersect1 Plane479, ToIntersect2 Plane481
  Intersect723: ToIntersect1 Plane479, ToIntersect2 Plane482
  Intersect724: ToIntersect1 Plane482, ToIntersect2 Plane480
  MultiSel37
  LineCorner37: Elements ({intersect ToIntersect1 Plane485, ToIntersect2 Intersect723}; {intersect ToIntersect1 Plane485, ToIntersect2 Intersect724}; {intersect ToIntersect1 Plane485, ToIntersect2 Intersect721}; {intersect ToIntersect1 Plane485, ToIntersect2 Intersect722})
  Pad146: profile LineCorner37, up to Plane483, opposite side up to Plane484, deactivated
  Plane486: type Offset, RefPlane Plane482, Offset 609.6 {= thickness}
  Plane487: type Offset, RefPlane Plane481, Offset 609.6 {= thickness}, reversed
  Plane488: type Offset, RefPlane Plane479, Offset 609.6 {= thickness}, reversed
  Plane489: type Offset, RefPlane Plane480, Offset 609.6 {= thickness}
  Plane490: type Offset, RefPlane Plane484, Offset 609.6 {= thickness}
  Plane491: type Offset, RefPlane Plane483, Offset 609.6 {= thickness}, reversed
  Intersect725: ToIntersect1 Plane486, ToIntersect2 Plane479
  Intersect726: ToIntersect1 Plane487, ToIntersect2 Plane479
  Intersect727: ToIntersect1 Plane490, ToIntersect2 Plane479
  Intersect728: ToIntersect1 Plane491, ToIntersect2 Plane479
  Trim433: Trimmed (Intersect725; Intersect728)
  Trim434: Trimmed (Trim433; Intersect726)
  Trim435: Trimmed (Trim434; Intersect727)
  Pocket150: profile Trim435, up to Plane489, deactivated
  Pad147: profile LineCorner37, up to Plane483, opposite side up to Plane484, deactivated
  Intersect729: ToIntersect1 Plane487, ToIntersect2 Plane480
  Intersect730: ToIntersect1 Plane480, ToIntersect2 Plane486
  Intersect731: ToIntersect1 Plane490, ToIntersect2 Plane480
  Intersect732: ToIntersect1 Plane491, ToIntersect2 Plane480
  Trim436: Trimmed (Intersect732; Intersect729)
  Trim437: Trimmed (Trim436; Intersect731)
  Trim438: Trimmed (Trim437; Intersect730)
  Pocket151: profile Trim438, up to Plane488, deactivated
  Intersect733: ToIntersect1 Plane489, ToIntersect2 Plane482
  Intersect734: ToIntersect1 Plane490, ToIntersect2 Plane482
  Intersect735: ToIntersect1 Plane482, ToIntersect2 Plane488
  Intersect736: ToIntersect1 Plane491, ToIntersect2 Plane482
  Trim439: Trimmed (Intersect733; Intersect736)
  Trim440: Trimmed (Trim439; Intersect735)
  Trim441: Trimmed (Trim440; Intersect734)
  Pad148: profile LineCorner37, up to Plane483, opposite side up to Plane484, deactivated
  Pocket152: profile Trim441, up to Plane487, deactivated
  Intersect737: ToIntersect1 Plane488, ToIntersect2 Plane481
  Intersect738: ToIntersect1 Plane490, ToIntersect2 Plane481
  Intersect739: ToIntersect1 Plane489, ToIntersect2 Plane481
  Intersect740: ToIntersect1 Plane491, ToIntersect2 Plane481
  Trim442: Trimmed (Intersect737; Intersect740)
  Trim443: Trimmed (Trim442; Intersect739)
  Trim444: Trimmed (Trim443; Intersect738)
  Pad149: profile LineCorner37, up to Plane483, opposite side up to Plane484, deactivated
  Pocket153: profile Trim444, up to Plane486, deactivated
Body39 "sugar_cube003Bc004"
  Line248: type PtDir, RefPoint Point28, Direction edge [XY plane of AxisSystem1 | ZX plane of AxisSystem1], Start 0, End 3657.6 {= Body39.X1}
  Line249: type PtDir, RefPoint Point28, Direction edge [XY plane of AxisSystem1 | ZX plane of AxisSystem1], Start 0, End 5181.6 {= Body39.X2}
  Line250: type PtDir, RefPoint Point28, Direction edge [YZ plane of AxisSystem1 | XY plane of AxisSystem1], Start 0, End 5181.6 {= Body39.Y1}
  Line251: type PtDir, RefPoint Point28, Direction edge [YZ plane of AxisSystem1 | XY plane of AxisSystem1], Start 0, End 3048 {= Body39.Y2}
  Line252: type PtDir, RefPoint Point28, Direction edge [ZX plane of AxisSystem1 | YZ plane of AxisSystem1], Start 0, End 4876.8 {= Body39.Z1}
  Line253: type PtDir, RefPoint Point28, Direction edge [ZX plane of AxisSystem1 | YZ plane of AxisSystem1], Start 0, End 4876.8 {= Body39.Z2}
  Plane492: type Normal, Curve Line248, RefPoint vertex of Line248
  Plane493: type Normal, Curve Line249, RefPoint vertex of Line249
  Plane494: type Normal, Curve Line250, RefPoint vertex of Line250
  Plane495: type Normal, Curve Line251, RefPoint vertex of Line251
  Plane496: type Normal, Curve Line252, RefPoint vertex of Line252
  Plane497: type Normal, Curve Line253, RefPoint vertex of Line253
  Plane498: type 3Points, Element1 Point28, Element2 vertex of Line250, Element3 vertex of Line248
  Intersect741: ToIntersect1 Plane494, ToIntersect2 Plane493
  Intersect742: ToIntersect1 Plane492, ToIntersect2 Plane494
  Intersect743: ToIntersect1 Plane492, ToIntersect2 Plane495
  Intersect744: ToIntersect1 Plane495, ToIntersect2 Plane493
  MultiSel38
  LineCorner38: Elements ({intersect ToIntersect1 Plane498, ToIntersect2 Intersect743}; {intersect ToIntersect1 Plane498, ToIntersect2 Intersect744}; {intersect ToIntersect1 Plane498, ToIntersect2 Intersect741}; {intersect ToIntersect1 Plane498, ToIntersect2 Intersect742})
  Pad150: profile LineCorner38, up to Plane496, opposite side up to Plane497
  Plane499: type Offset, RefPlane Plane495, Offset 609.6 {= thickness}
  Plane500: type Offset, RefPlane Plane494, Offset 609.6 {= thickness}, reversed
  Plane501: type Offset, RefPlane Plane492, Offset 609.6 {= thickness}, reversed
  Plane502: type Offset, RefPlane Plane493, Offset 609.6 {= thickness}
  Plane503: type Offset, RefPlane Plane497, Offset 609.6 {= thickness}
  Plane504: type Offset, RefPlane Plane496, Offset 609.6 {= thickness}, reversed
  Intersect745: ToIntersect1 Plane499, ToIntersect2 Plane492
  Intersect746: ToIntersect1 Plane500, ToIntersect2 Plane492
  Intersect747: ToIntersect1 Plane503, ToIntersect2 Plane492
  Intersect748: ToIntersect1 Plane504, ToIntersect2 Plane492
  Trim445: Trimmed (Intersect745; Intersect748)
  Trim446: Trimmed (Trim445; Intersect746)
  Trim447: Trimmed (Trim446; Intersect747)
  Pocket154: profile Trim447, up to Plane502, deactivated
  Pad151: profile LineCorner38, up to Plane496, opposite side up to Plane497, deactivated
  Intersect749: ToIntersect1 Plane500, ToIntersect2 Plane493
  Intersect750: ToIntersect1 Plane493, ToIntersect2 Plane499
  Intersect751: ToIntersect1 Plane503, ToIntersect2 Plane493
  Intersect752: ToIntersect1 Plane504, ToIntersect2 Plane493
  Trim448: Trimmed (Intersect752; Intersect749)
  Trim449: Trimmed (Trim448; Intersect751)
  Trim450: Trimmed (Trim449; Intersect750)
  Pocket155: profile Trim450, up to Plane501, deactivated
  Intersect753: ToIntersect1 Plane502, ToIntersect2 Plane495
  Intersect754: ToIntersect1 Plane503, ToIntersect2 Plane495
  Intersect755: ToIntersect1 Plane495, ToIntersect2 Plane501
  Intersect756: ToIntersect1 Plane504, ToIntersect2 Plane495
  Trim451: Trimmed (Intersect753; Intersect756)
  Trim452: Trimmed (Trim451; Intersect755)
  Trim453: Trimmed (Trim452; Intersect754)
  Pad152: profile LineCorner38, up to Plane496, opposite side up to Plane497, deactivated
  Pocket156: profile Trim453, up to Plane500, deactivated
  Intersect757: ToIntersect1 Plane501, ToIntersect2 Plane494
  Intersect758: ToIntersect1 Plane503, ToIntersect2 Plane494
  Intersect759: ToIntersect1 Plane502, ToIntersect2 Plane494
  Intersect760: ToIntersect1 Plane504, ToIntersect2 Plane494
  Trim454: Trimmed (Intersect757; Intersect760)
  Trim455: Trimmed (Trim454; Intersect759)
  Trim456: Trimmed (Trim455; Intersect758)
  Pad153: profile LineCorner38, up to Plane496, opposite side up to Plane497, deactivated
  Pocket157: profile Trim456, up to Plane499, deactivated
Body40 "sugar_cube003Bd004"
  Line254: type PtDir, RefPoint Point24, Direction edge [XY plane of AxisSystem1 | ZX plane of AxisSystem1], Start 0, End 3657.6 {= Body40.X1}
  Line255: type PtDir, RefPoint Point24, Direction edge [XY plane of AxisSystem1 | ZX plane of AxisSystem1], Start 0, End 3352.8 {= Body40.X2}
  Line256: type PtDir, RefPoint Point24, Direction edge [YZ plane of AxisSystem1 | XY plane of AxisSystem1], Start 0, End 5486.4 {= Body40.Y1}
  Line257: type PtDir, RefPoint Point24, Direction edge [YZ plane of AxisSystem1 | XY plane of AxisSystem1], Start 0, End 6096 {= Body40.Y2}
  Line258: type PtDir, RefPoint Point24, Direction edge [ZX plane of AxisSystem1 | YZ plane of AxisSystem1], Start 0, End 5181.6 {= Body40.Z1}
  Line259: type PtDir, RefPoint Point24, Direction edge [ZX plane of AxisSystem1 | YZ plane of AxisSystem1], Start 0, End 4267.2 {= Body40.Z2}
  Plane505: type Normal, Curve Line254, RefPoint vertex of Line254
  Plane506: type Normal, Curve Line255, RefPoint vertex of Line255
  Plane507: type Normal, Curve Line256, RefPoint vertex of Line256
  Plane508: type Normal, Curve Line257, RefPoint vertex of Line257
  Plane509: type Normal, Curve Line258, RefPoint vertex of Line258
  Plane510: type Normal, Curve Line259, RefPoint vertex of Line259
  Plane511: type 3Points, Element1 Point24, Element2 vertex of Line256, Element3 vertex of Line254
  Intersect761: ToIntersect1 Plane507, ToIntersect2 Plane506
  Intersect762: ToIntersect1 Plane505, ToIntersect2 Plane507
  Intersect763: ToIntersect1 Plane505, ToIntersect2 Plane508
  Intersect764: ToIntersect1 Plane508, ToIntersect2 Plane506
  MultiSel39
  LineCorner39: Elements ({intersect ToIntersect1 Plane511, ToIntersect2 Intersect763}; {intersect ToIntersect1 Plane511, ToIntersect2 Intersect764}; {intersect ToIntersect1 Plane511, ToIntersect2 Intersect761}; {intersect ToIntersect1 Plane511, ToIntersect2 Intersect762})
  Pad154: profile LineCorner39, up to Plane509, opposite side up to Plane510
  Plane512: type Offset, RefPlane Plane508, Offset 609.6 {= thickness}
  Plane513: type Offset, RefPlane Plane507, Offset 609.6 {= thickness}, reversed
  Plane514: type Offset, RefPlane Plane505, Offset 609.6 {= thickness}, reversed
  Plane515: type Offset, RefPlane Plane506, Offset 609.6 {= thickness}
  Plane516: type Offset, RefPlane Plane510, Offset 609.6 {= thickness}
  Plane517: type Offset, RefPlane Plane509, Offset 609.6 {= thickness}, reversed
  Intersect765: ToIntersect1 Plane512, ToIntersect2 Plane505
  Intersect766: ToIntersect1 Plane513, ToIntersect2 Plane505
  Intersect767: ToIntersect1 Plane516, ToIntersect2 Plane505
  Intersect768: ToIntersect1 Plane517, ToIntersect2 Plane505
  Trim457: Trimmed (Intersect765; Intersect768)
  Trim458: Trimmed (Trim457; Intersect766)
  Trim459: Trimmed (Trim458; Intersect767)
  Pocket158: profile Trim459, up to Plane515, deactivated
  Pad155: profile LineCorner39, up to Plane509, opposite side up to Plane510, deactivated
  Intersect769: ToIntersect1 Plane513, ToIntersect2 Plane506
  Intersect770: ToIntersect1 Plane506, ToIntersect2 Plane512
  Intersect771: ToIntersect1 Plane516, ToIntersect2 Plane506
  Intersect772: ToIntersect1 Plane517, ToIntersect2 Plane506
  Trim460: Trimmed (Intersect772; Intersect769)
  Trim461: Trimmed (Trim460; Intersect771)
  Trim462: Trimmed (Trim461; Intersect770)
  Pocket159: profile Trim462, up to Plane514, deactivated
  Intersect773: ToIntersect1 Plane515, ToIntersect2 Plane508
  Intersect774: ToIntersect1 Plane516, ToIntersect2 Plane508
  Intersect775: ToIntersect1 Plane508, ToIntersect2 Plane514
  Intersect776: ToIntersect1 Plane517, ToIntersect2 Plane508
  Trim463: Trimmed (Intersect773; Intersect776)
  Trim464: Trimmed (Trim463; Intersect775)
  Trim465: Trimmed (Trim464; Intersect774)
  Pad156: profile LineCorner39, up to Plane509, opposite side up to Plane510, deactivated
  Pocket160: profile Trim465, up to Plane513, deactivated
  Intersect777: ToIntersect1 Plane514, ToIntersect2 Plane507
  Intersect778: ToIntersect1 Plane516, ToIntersect2 Plane507
  Intersect779: ToIntersect1 Plane515, ToIntersect2 Plane507
  Intersect780: ToIntersect1 Plane517, ToIntersect2 Plane507
  Trim466: Trimmed (Intersect777; Intersect780)
  Trim467: Trimmed (Trim466; Intersect779)
  Trim468: Trimmed (Trim467; Intersect778)
  Pad157: profile LineCorner39, up to Plane509, opposite side up to Plane510, deactivated
  Pocket161: profile Trim468, up to Plane512, deactivated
